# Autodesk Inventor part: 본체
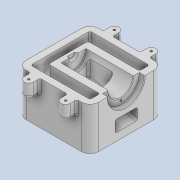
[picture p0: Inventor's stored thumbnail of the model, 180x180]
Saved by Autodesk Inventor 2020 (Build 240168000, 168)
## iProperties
Created: 2022-03
Part Number: 본체
Material: 일반
Document SubType Name: Modeling
Designer: Administrator
Density: 1 g/cm^3
Appearance: 기본값
Author: Administrator
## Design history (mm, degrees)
sketch "스케치1"
  geometry: L1 (-55, 55)-(55, 55); L2 (55, 55)-(55, -55); L3 (55, -55)-(-55, -55); L4 (-55, -55)-(-55, 55); L5 (-55, 55)-(55, -55); L6 (55, 55)-(-55, -55); 1 further point
  constraints: 12 end point, 2 midpoint, 2 parallel, 1 horizontal, 1 perpendicular
  dimensions: "d0" = 110 distance of L1.end L2.end; "d1" = 110 distance of L2.end L3.end
extrude "돌출1" new body sketch "스케치1" distance "d2" = 65; taper "d3" = 0 deg
fillet "모깎기1" dims "d4" = 13
sketch "스케치2"
  geometry: L1 (-55, 42)-(-55, -42) reference; L2 (-42, -55)-(42, -55) reference; L3 (55, -42)-(55, 42) reference; L4 (42, 55)-(-42, 55) reference; L5 (-45, -45)-(45, -45); L6 (45, -45)-(45, -30); L7 (45, -30)-(-33, -30); L8 (-33, -30)-(-33, 30); L9 (-33, 30)-(45, 30); L10 (45, 30)-(45, 45); L11 (45, 45)-(-45, 45); L12 (-45, 45)-(-45, -45); 2 further points
  constraints: 16 end point, 6 perpendicular, 2 point on line, 1 horizontal, 1 horizontal alignment, 1 midpoint
  dimensions: "d5" = 10 distance between parallel lines of L12 L1; "d6" = 10 distance between parallel lines of L4 L11; "d7" = 10 distance between parallel lines of L2 L5; "d8" = 10 distance between parallel lines of L3 L10; "d9" = 60 distance of L7.end L8.end; "d10" = 22 distance between parallel lines of L8 L1
extrude "돌출2" cut sketch "스케치2" extent not by distance; stored distance "d11" = 0; taper "d12" = 0 deg
fillet "모깎기2" dims "d13" = 3
sketch "스케치3"
  geometry: L1 (0, 65)-(84, 65) reference; C1 r 28 at (42, 65); C2 r 19 at (42, 65); 1 further point
  constraints: 2 centre point, 1 coincident, 1 midpoint
  dimensions: "d14" = 56 diameter of C1; "d15" = 38 diameter of C2
extrude "돌출3" cut sketch "스케치3" distance "d16" = 8; taper "d17" = 0 deg
extrude "돌출4" cut sketch "스케치3" distance "d18" = 80; taper "d19" = 0 deg
sketch "스케치4"
  geometry: L1 (-25, -19)-(-25, 19) reference; L2 (-25, -7.5)-(-29, -5.191); L3 (-29, -5.191)-(-29, 0); L4 (-32.5, 0)-(-25, 0); A1 r 7.5 centre (-25, 0) between (-25, -7.5) and (-32.5, 0); 1 further point
  constraints: 6 end point, 2 point on circle, 2 point on line, 1 centre point, 1 horizontal, 1 midpoint, 1 vertical
  dimensions: "d20" = 15 diameter of A1; "d22" = 30 deg angle of L2 L4; "d23" = 4 distance between parallel lines of L1 L3
revolve "회전1" sketch "스케치4" stored, may be unused: angle "d24" = 90 deg
fillet "모깎기3" dims "d25" = 1
sketch "스케치5"
  geometry: L1 (-30, 0)-(45, 0) reference; L2 (-33, 30)-(35.578, 11.625); L3 (-33, 0)-(-33, 65) reference; L4 (-19, 72.47)-(-19, 31.425); L5 (19, 38.843)-(19, 72.47); L6 (19, 72.47)-(-19, 72.47); L7 (55, 65)-(55, 37) reference; L8 (19, 38.843)-(69.602, 25.284); L9 (-19, 31.425)-(65.202, 8.863); L10 (65.202, 8.863)-(69.602, 25.284); 2 further points
  constraints: 14 end point, 2 perpendicular, 1 parallel, 1 point on line, 1 vertical
  dimensions: "d27" = 30 distance from line of L1 L2.start; "d28" = 75 deg angle of L3 L2; "d30" = 38 distance of L5.end L4.start; "d31" = 36 distance between parallel lines of L7 L5; "d34" = 5 distance between parallel lines of L2 L9; "d35" = 17 distance between parallel lines of L9 L8
extrude "돌출5" cut sketch "스케치5" stored distance "d32" = 34; taper "d33" = 0 deg
sketch "스케치6"
  geometry: L1 (-33, 30)-(45, 9.1); L2 (-33, 0)-(-33, 65) reference; L3 (-42, 0)-(-55, 0) reference; L4 (45, 9.1)-(45, 0); L5 (45, 0)-(-33, 0); L6 (55, 65)-(55, 0) reference; L7 (55, 0)-(42, 0) reference; L8 (-33, 30)-(-33, 0); 1 further point
  constraints: 8 end point, 2 collinear, 1 perpendicular, 1 point on line, 1 vertical
  dimensions: "d36" = 75 deg angle of L2 L1; "d37" = 30 distance from line of L3 L1.start; "d39" = 10 distance between parallel lines of L6 L4
extrude "돌출6" cut sketch "스케치6" stored distance "d40" = 62; taper "d41" = 0 deg
extrude "돌출7" cut sketch "스케치6" stored distance "d42" = 62; taper "d43" = 0 deg
fillet "모깎기5" dims "d45" = 3
chamfer "모따기1" distance "d46" = 1; stored, may be unused: second distance "d47" = 2, angle "d48" = 45 deg
fillet "모깎기6" dims "d49" = 3
fillet "모깎기7" dims "d50" = 3
fillet "모깎기8" dims "d51" = 3
sketch "스케치7"
  geometry: L1 (-55, 42)-(-55, -42) reference; L2 (-42, -55)-(42, -55) reference; L3 (-35, -65)-(-35, -47.597); L4 (-21, -65)-(-21, -47.597); L5 (-35, -47.597)-(-21, -47.597); L6 (-35, 65)-(-35, 50.14); L7 (-35, 50.14)-(-21, 50.14); L8 (-21, 50.14)-(-21, 65); L9 (21, -65)-(21, -49.94); L10 (21, -49.94)-(35, -49.94); L11 (35, -49.94)-(35, -65); L12 (35, 65)-(35, 49); L13 (21, 65)-(21, 49); L14 (21, 49)-(35, 49); A1 r 7 centre (-28, -65) between (-35, -65) and (-21, -65); A2 r 7 centre (-28, 65) between (-35, 65) and (-21, 65); A3 r 7 centre (28, -65) between (21, -65) and (35, -65); A4 r 7 centre (28, 65) between (35, 65) and (21, 65); 1 further point
  constraints: 24 end point, 8 point on circle, 8 tangent, 4 centre point, 4 perpendicular, 4 vertical, 2 horizontal, 2 point on line, 2 vertical alignment
  dimensions: "d52" = 14 diameter of A1; "d53" = 27 distance from line of A1.centre L1; "d54" = 14 diameter of A2; "d55" = 130 distance of A1.centre A2.centre; "d56" = 65 vertical distance of point (0, 0) A1.centre; "d57" = 14 diameter of A3; "d58" = 14 diameter of A4; "d59" = 130 distance of A3.centre A4.centre; "d60" = 56 distance of A3.centre A1.centre; "d61" = 65 vertical distance of point (0, 0) A3.centre
extrude "돌출8" join sketch "스케치7" distance "d62" = 20; taper "d63" = 0 deg
fillet "모깎기9" dims "d64" = 3
fillet "모깎기10" dims "d65" = 3
sketch "스케치8"
  geometry: A1 r 7 centre (28, 65) between (35, 65) and (21, 65) reference; A2 r 7 centre (-28, 65) between (-21, 65) and (-35, 65) reference; A3 r 7 centre (28, -65) between (21, -65) and (35, -65) reference; A4 r 7 centre (-28, -65) between (-35, -65) and (-21, -65) reference; 5 further points
  constraints: 4 coincident
hole "구멍1" sketch "스케치8" at (28, 65), (-28, 65), (28, -65), (-28, -65) diameter "d66" = 3.242; stored, may be unused: countersink angle "d70" = 90 deg, drill point angle "d72" = 118 deg; dims "d67" = 9, "d68" = 4, "d69" = 2, "d71" = 11
sketch "스케치9" dims "d73" = 46
  geometry: A1 r 20 centre (42, 65) between (22, 65) and (62, 65) reference; A2 r 28 centre (42, 65) between (14, 65) and (70, 65) reference; 3 further points
  constraints: 2 vertical alignment, 1 coincident, 2 other
hole "구멍2" sketch "스케치9" at (42, 42) diameter "d74" = 3.242; stored, may be unused: countersink angle "d78" = 90 deg, drill point angle "d80" = 118 deg; dims "d75" = 9, "d76" = 4, "d77" = 2, "d79" = 11
sketch "스케치10"
  geometry: L1 (0, 0)-(84, 0) reference; L2 (-13, 65)-(-13, 0) reference; 2 further points
  constraints: 1 other
  dimensions: "d81" = 20 distance from line of point (42, 20) L1; "d82" = 55 distance from line of point (42, 20) L2
feature "엠보싱1" sketch "스케치10" dims "d0" = 110, "d1" = 110, "d83" = 0.5, "d84" = 0
node "솔리드1"
feature "A9D066F2-1C7D-4E18-AEED-F7BC21143FA4" dims "d66" = 3.242, "d67" = 9, "d68" = 4, "d69" = 2, "d70" = 90 deg, "d71" = 11, "d72" = 118 deg
